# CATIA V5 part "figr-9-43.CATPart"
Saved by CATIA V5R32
Part number: Part1
Bounding box of the stored display mesh (mm): x -60 to 60, y -70.327 to 65.87, z 0 to 125
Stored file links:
  D:\PROJECTS\Project 2022\CATIA V5 6R 2022\Resources\Part Files\c09_catia_v5_6r2022_prt\c09_catia_v5_6r2022_prt\figr-9-43.CATPart
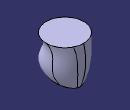
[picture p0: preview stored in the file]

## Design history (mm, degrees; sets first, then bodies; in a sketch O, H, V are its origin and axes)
Set1
  Plane1: type Offset, RefPlane xy-plane, Offset 125
Body1 (main body)
  Sketch1 on xy-plane, origin (0, 0, 0), H (1, 0, 0), V (0, 1, 0)
    ellipse A1 centre (0, 0) semi-axes 50, 30 rotation 270
    point P1 (30, 0)
    coincidence: P1 H, A1 P1
  Sketch2 on Plane1, origin (0, 0, 125), H (1, 0, 0), V (0, 1, 0)
    circle A1 centre (0, 0) radius 60
  Sketch3 on yz-plane, origin (0, 0, 0), H (0, 1, 0), V (0, 0, 1)
    arc A1 centre (-129.6632, 77.2731) radius 195.5761 from (50, 0) to (60, 125) ccw
    point P2 (50, 0)
    point P3 (60, 125)
    reference projected line E1 (-50, 0) -> (50, 0) from edge of Sketch1
    reference projected line E2 (-60, 125) -> (60, 125) from edge of Sketch2
    coincidence: P2 H, P2 E1, P3 E2
  Sketch4 on yz-plane, origin (0, 0, 0), H (0, 1, 0), V (0, 0, 1)
    spline S1 through (-50, 0) (-70, 40) (-50, 100) (-60, 125)
    reference projected line E1 (-60, 125) -> (60, 125) from edge of Sketch2
    reference projected line E2 (-50, 0) -> (50, 0) from edge of Sketch1
    point P1 (-60, 125)
    point P2 (-50, 0)
    coincidence: P1 E1, P2 E2
  Loft1: Sections (Sketch1; Sketch2), Guides (Sketch3; Sketch4)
